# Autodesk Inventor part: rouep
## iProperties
Shininess: 69.0
Length Units: 11269
Angle Units: 11279
Time Units: 11290
Mass Units: 11283
Length Display Precision: 3
Angle Display Precision: 2
Compacted: True
Created: 2001-12
Part Number: rouep
Material: Par défaut
Document SubType Name: Modélisation
Designer: pichon
Density: 0.0
Volumn: 0.0
Area: 0.0
PropertySet Name: Model Information
Control State: 0
Master: False
Checked Out: False
Author: pichon
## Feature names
1. Révolution2 [Revolution]
